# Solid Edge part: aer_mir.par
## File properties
Author: Kasutaja
Template: Ansi Inch Part.par
Last saved by: Kasutaja
Revision: 2
Application: Solid Edge
Accuracy: 0,990
Username: Kasutaja
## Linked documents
aer.par
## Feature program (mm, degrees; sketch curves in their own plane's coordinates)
part copy "CopiedPart_1"
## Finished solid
Body 1: solid body, 8 faces, 12 edges, 6 vertices.
  Faces by surface: blend 3, spline 3, plane 2
  Edges by curve: curve on surface 6, intersection 6
Bounding box of the edges (mm; curved faces can reach further): 9.363 x 230.812 x 18.909, from (-4.6814, 0, -9.4545) to (4.6813, 230.8122, 9.4544).
Planar faces by outward normal: +y 1, -y 1
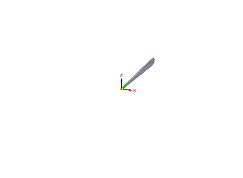
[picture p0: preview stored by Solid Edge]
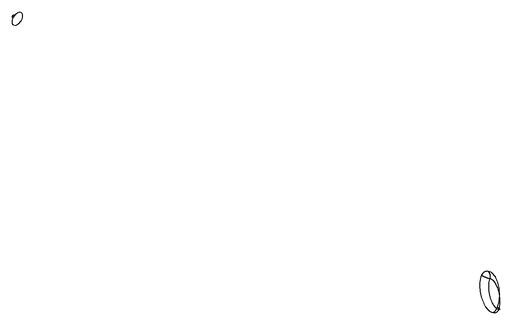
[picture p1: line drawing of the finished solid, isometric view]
